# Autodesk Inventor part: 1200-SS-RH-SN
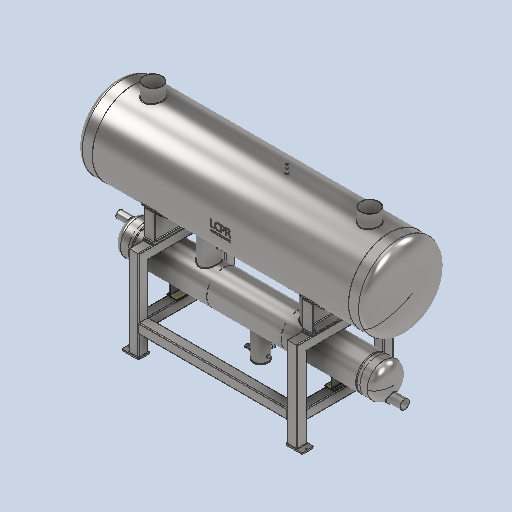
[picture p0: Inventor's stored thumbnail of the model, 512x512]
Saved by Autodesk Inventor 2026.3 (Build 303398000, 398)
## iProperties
Created: 2026-05
Part Number: 1200-SS-RH-SN
Material: Generic
Document SubType Name: Modeling
Designer: rva
Density: 1 g/cm^3
Appearance: Default
Author: rva
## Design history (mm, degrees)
derived "LCPR-SS-1200-RH-SN.iam"
body "Solid1"
node "Sub-SS-500-250-3326-294-125-100-RH.iam:1::LCPR-SS-500 mm Sub"
node "Sub-SS-500-250-3326-294-125-100-RH.iam:1::LCPR-SS-500 mm Sub"
node "Sub-SS-500-250-3326-294-125-100-RH.iam:1::H1100-R.ipt:1"
node "Sub-SS-500-250-3326-294-125-100-RH.iam:1::1-2 Inch NPT Socke"
node "Sub-SS-500-250-3326-294-125-100-RH.iam:1::Welds"
node "LCPR-SS-1200-Frame Assembly.iam:1::LCPR-SS_170 x 250 Foot Pl"
node "LCPR-SS-1200-Frame Assembly.iam:1::LCPR-SS_170 x 250 Foot Pl"
node "LCPR-SS-1200-Frame Assembly.iam:1::LCPR-SS_170 x 250 Foot Pl"
node "LCPR-SS-1200-Frame Assembly.iam:1::LCPR-SS_170 x 250 Foot Pl"
node "LCPR-SS-1200-Frame Assembly.iam:1::Welds"
node "AS 1112 - M20(2).ipt:1"
node "AS 1237 (4.2) 20 mm:1"
node "AS 1111 - Metric M20 x 200:1"
node "AS 1112 - M20(2).ipt:2"
node "AS 1237 (4.2) 20 mm:3"
node "AS 1111 - Metric M20 x 200:2"
node "AS 1112 - M20(2).ipt:3"
node "AS 1237 (4.2) 20 mm:5"
node "AS 1111 - Metric M20 x 200:3"
node "AS 1112 - M20(2).ipt:4"
node "AS 1237 (4.2) 20 mm:7"
node "AS 1111 - Metric M20 x 200:4"
node "Nylon Heat Tranfer Spacer 1028 x 150.ipt:1"
node "Nylon Heat Tranfer Spacer 1028 x 150.ipt:2"
node "LCPR-SS-1200-3800-250-SN-WELD.iam:1::LCPR-LOGO.ipt:1"
node "LCPR-SS-1200-3800-250-SN-WELD.iam:1::H1100-R.ipt:1"
node "LCPR-SS-1200-3800-250-SN-WELD.iam:1::1200 mm-SS-Dome End Cap"
node "LCPR-SS-1200-3800-250-SN-WELD.iam:1::LCPR-SS-1200-Leg Assemb"
node "LCPR-SS-1200-3800-250-SN-WELD.iam:1::LCPR-SS-1200-Leg Assemb"
node "LCPR-SS-1200-3800-250-SN-WELD.iam:1::1200 mm-SS-Dome End Cap"
node "LCPR-SS-1200-3800-250-SN-WELD.iam:1::Welds"
node "Nylon Heat Tranfer Spacer 300 x 150.ipt:1"
node "Nylon Heat Tranfer Spacer 300 x 150.ipt:2"
node "LCPR-SS-1200-RH-SN.iam_Bodies"
